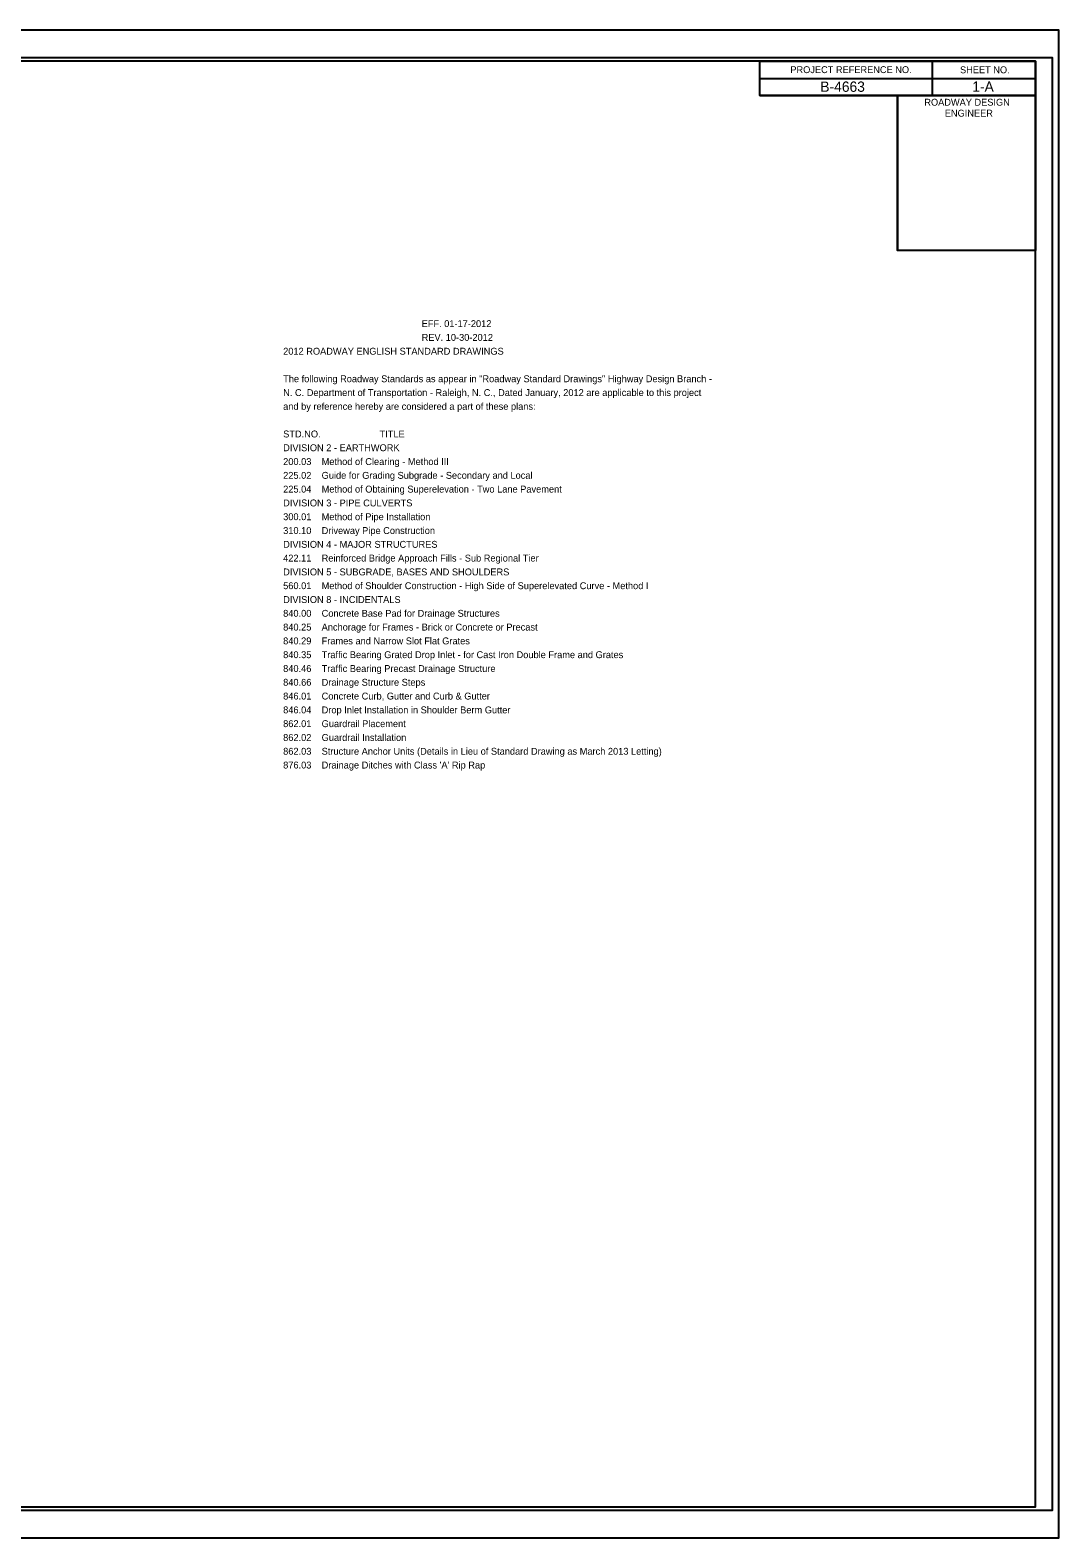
# Model space of a CAD drawing. Extents: x 573852.2 to 573885.9, y -53312.9 to -53240.3.
# Drawn here: x 573870.93 to 573885.86, y -53262.19 to -53240.29 of the extents above; entities that cross this region are included whole.
import ezdxf

# ---------------------------------------------------------------- set-up
doc = ezdxf.new("R2010")
doc.units = 0
for name, color, linetype in [('Default', 7, 'Continuous'), ('Sheet Cutting Line CELL', 7, 'Continuous'), ('Sheet Data Field CELL', 7, 'Continuous'), ('Sheet Plan CELL', 7, 'Continuous'), ('Sheet Plot Border Inside CELL', 7, 'Continuous'), ('Sheet Plot Border Outside CELL', 7, 'Continuous')]:
    doc.layers.add(name, color=color, linetype=linetype)

msp = doc.modelspace()

# ---------------------------------------------------------------- linework, layer by layer
at = {"layer": 'Sheet Cutting Line CELL'}
for p, q in [((573885.861, -53240.29), (573852.191, -53240.29)), ((573852.191, -53262.19), (573885.861, -53262.19))]:
    msp.add_line(p, q, dxfattribs=at)
at = {"layer": 'Sheet Plan CELL'}
for p, q in [((573884.021, -53240.741), (573884.021, -53241.241)), ((573881.52, -53240.991), (573885.521, -53240.991)), ((573881.52, -53241.241), (573885.521, -53241.241)), ((573881.52, -53241.241), (573885.521, -53241.241)), ((573883.521, -53241.241), (573883.521, -53243.49))]:
    msp.add_line(p, q, dxfattribs=at)
for points in [[(573885.521, -53240.74), (573855.521, -53240.74), (573855.521, -53261.74), (573885.521, -53261.74)], [(573881.52, -53240.74), (573885.521, -53240.74), (573885.521, -53241.241), (573881.52, -53241.241)], [(573883.521, -53241.241), (573885.521, -53241.241), (573885.521, -53243.491), (573883.521, -53243.491)]]:
    msp.add_lwpolyline(points, close=True, dxfattribs=at)
at = {"layer": 'Sheet Plot Border Inside CELL'}
msp.add_lwpolyline([(573852.451, -53261.79), (573885.771, -53261.79), (573885.771, -53240.69), (573852.451, -53240.69)], close=True, dxfattribs=at)
at = {"layer": 'Sheet Plot Border Outside CELL'}
msp.add_lwpolyline([(573852.191, -53262.19), (573885.861, -53262.19), (573885.861, -53240.29), (573852.191, -53240.29)], close=True, dxfattribs=at)

# ---------------------------------------------------------------- texts
at = {"layer": 'Default'}
for s, height, p in [('                                                      EFF. 01-17-2012', 0.1002, (573874.601, -53244.603)), ('                                                      REV. 10-30-2012', 0.1002, (573874.601, -53244.803)), ('2012 ROADWAY ENGLISH STANDARD DRAWINGS', 0.1002, (573874.601, -53245.004)), ('The following Roadway Standards as appear in "Roadway Standard Drawings" Highway Design Branch -', 0.1002, (573874.601, -53245.404)), ('N. C. Department of Transportation - Raleigh, N. C., Dated January, 2012 are applicable to this project', 0.100195, (573874.601, -53245.605)), ('and by reference hereby are considered a part of these plans:', 0.1002, (573874.601, -53245.805)), ('STD.NO.                       TITLE', 0.1002, (573874.601, -53246.206)), ('DIVISION 2 - EARTHWORK', 0.1002, (573874.601, -53246.406)), ('200.03    Method of Clearing - Method III', 0.1002, (573874.601, -53246.607)), ('225.02    Guide for Grading Subgrade - Secondary and Local', 0.1002, (573874.601, -53246.807)), ('225.04    Method of Obtaining Superelevation - Two Lane Pavement', 0.1002, (573874.601, -53247.007)), ('DIVISION 3 - PIPE CULVERTS', 0.1002, (573874.601, -53247.208)), ('300.01    Method of Pipe Installation ', 0.1002, (573874.601, -53247.408)), ('310.10    Driveway Pipe Construction', 0.1002, (573874.601, -53247.609)), ('DIVISION 4 - MAJOR STRUCTURES', 0.1002, (573874.601, -53247.809)), ('422.11    Reinforced Bridge Approach Fills - Sub Regional Tier', 0.1002, (573874.601, -53248.009)), ('560.01    Method of Shoulder Construction - High Side of Superelevated Curve - Method I', 0.1002, (573874.601, -53248.41)), ('DIVISION 5 - SUBGRADE, BASES AND SHOULDERS', 0.1002, (573874.601, -53248.21)), ('DIVISION 8 - INCIDENTALS', 0.1002, (573874.601, -53248.611)), ('840.00    Concrete Base Pad for Drainage Structures', 0.1002, (573874.601, -53248.811)), ('840.25    Anchorage for Frames - Brick or Concrete or Precast', 0.1002, (573874.601, -53249.011)), ('840.29    Frames and Narrow Slot Flat Grates', 0.1002, (573874.601, -53249.212)), ('840.35    Traffic Bearing Grated Drop Inlet - for Cast Iron Double Frame and Grates', 0.1002, (573874.601, -53249.412)), ('840.46    Traffic Bearing Precast Drainage Structure', 0.1002, (573874.601, -53249.613)), ('840.66    Drainage Structure Steps', 0.1002, (573874.601, -53249.813)), ('846.01    Concrete Curb, Gutter and Curb & Gutter', 0.1002, (573874.601, -53250.013)), ('846.04    Drop Inlet Installation in Shoulder Berm Gutter', 0.1002, (573874.601, -53250.214)), ('862.01    Guardrail Placement', 0.1002, (573874.601, -53250.414)), ('862.02    Guardrail Installation', 0.1002, (573874.601, -53250.615)), ('862.03    Structure Anchor Units (Details in Lieu of Standard Drawing as March 2013 Letting)', 0.1002, (573874.601, -53250.815)), ("876.03    Drainage Ditches with Class 'A' Rip Rap", 0.1002, (573874.601, -53251.015))]:
    msp.add_text(s, height=height, dxfattribs=at).set_placement(p)
at = {"layer": 'Sheet Data Field CELL'}
for s, p in [('B-4663', (573882.399, -53241.186)), ('1-A', (573884.605, -53241.185))]:
    msp.add_text(s, height=0.15, dxfattribs=at).set_placement(p)
at = {"layer": 'Sheet Plan CELL'}
for s, p in [('PROJECT REFERENCE NO.', (573881.964, -53240.914)), ('SHEET NO.', (573884.427, -53240.916)), ('ROADWAY DESIGN', (573883.909, -53241.387)), ('ENGINEER', (573884.206, -53241.546))]:
    msp.add_text(s, height=0.1, dxfattribs=at).set_placement(p)

doc.saveas('drawing.dxf')
